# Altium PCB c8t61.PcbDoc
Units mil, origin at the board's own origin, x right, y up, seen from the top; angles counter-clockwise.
Board outline 3290 x 3191.61 mil, 2 copper layers (Top Layer, Bottom Layer); 81 components, 47 nets, 395 pads, 83 vias.
Unrouted connection lines stored in the file: 7.
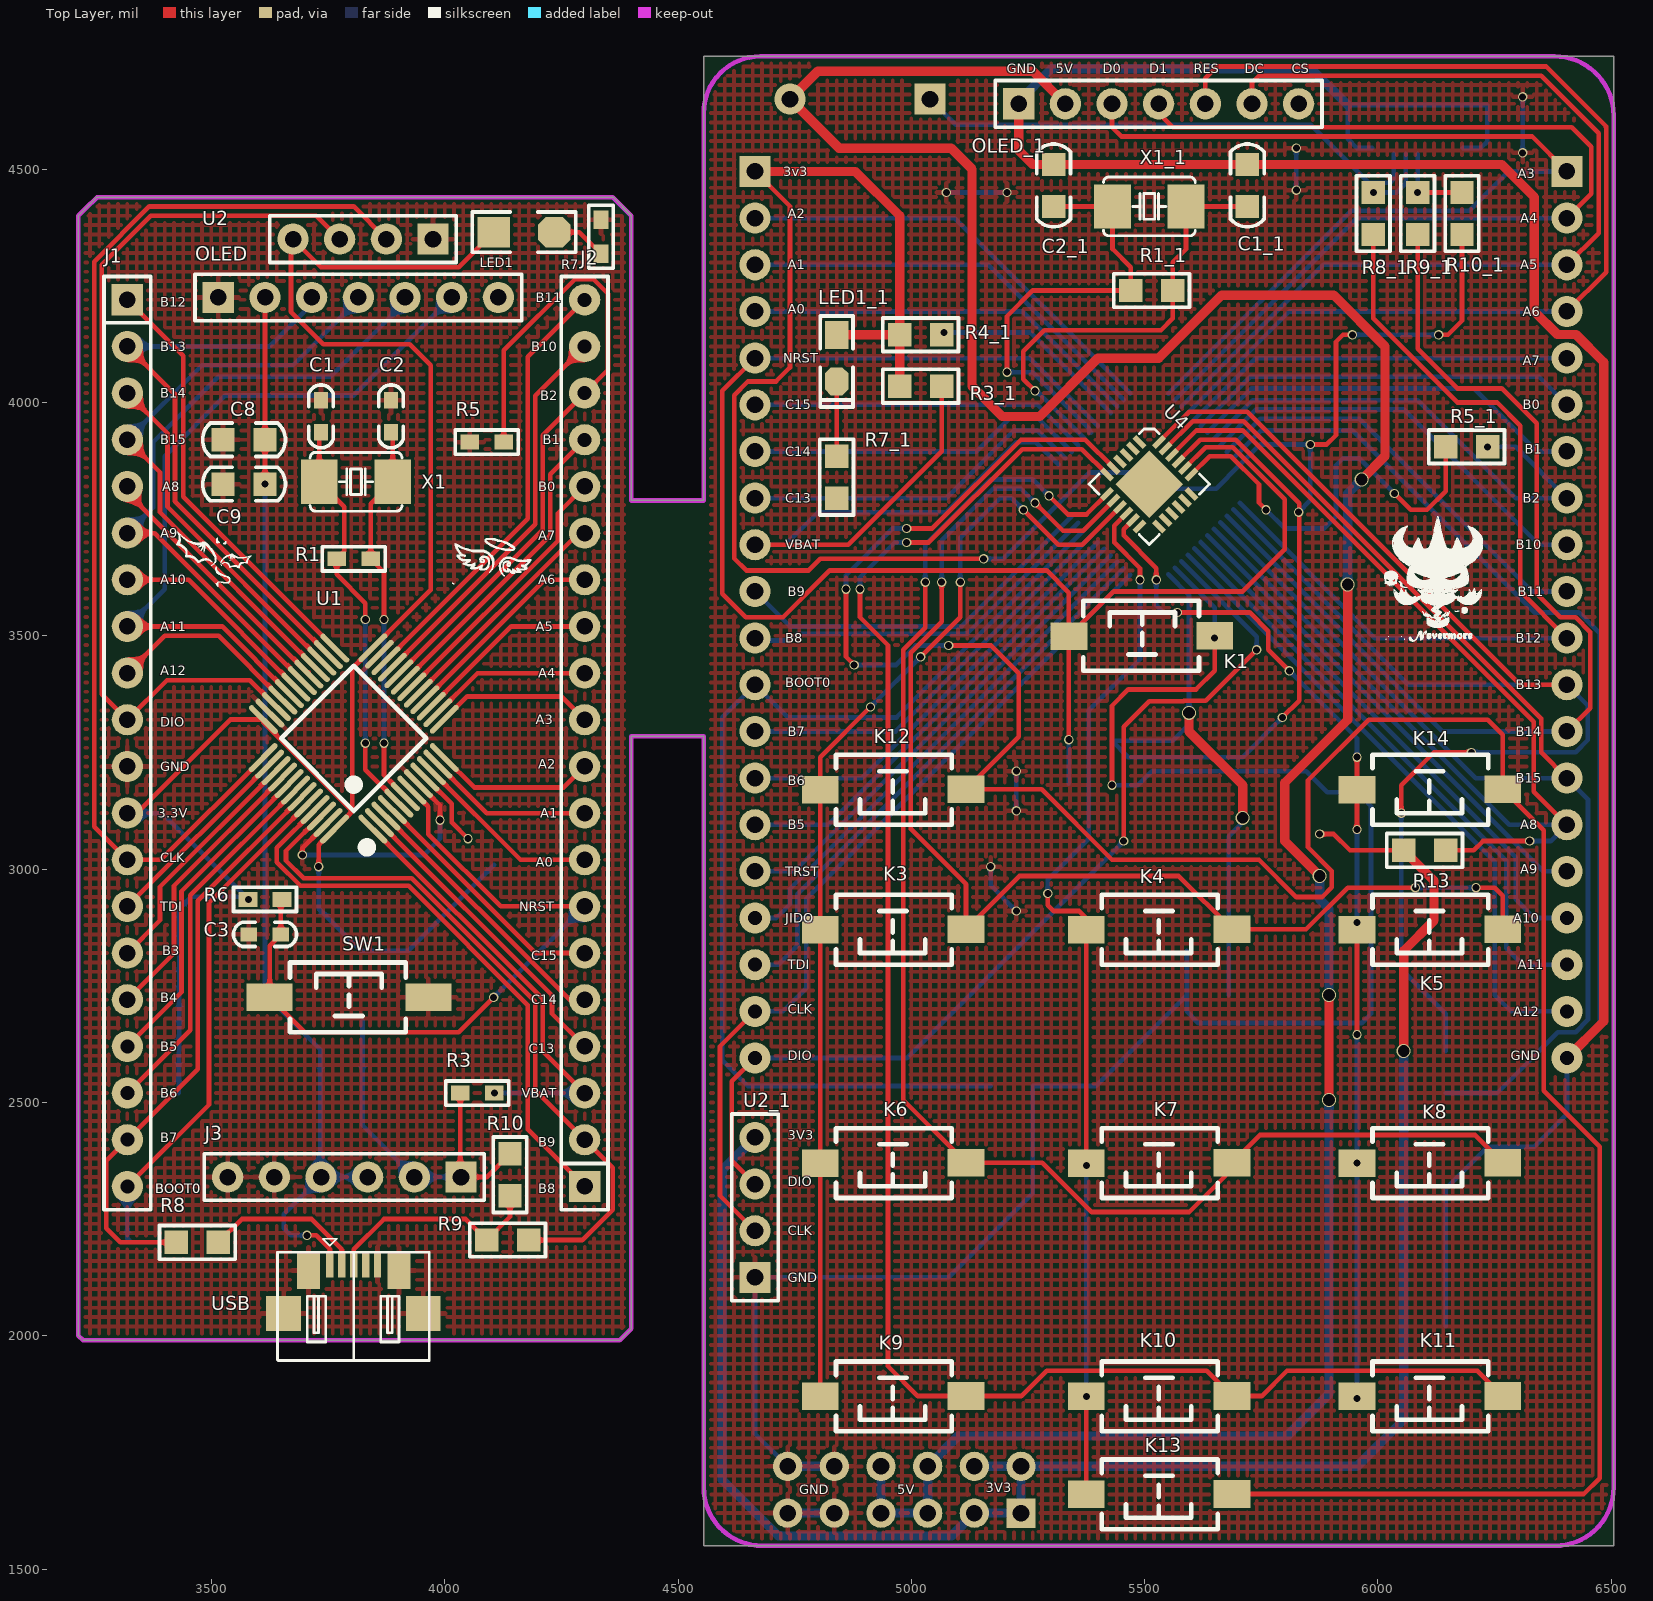
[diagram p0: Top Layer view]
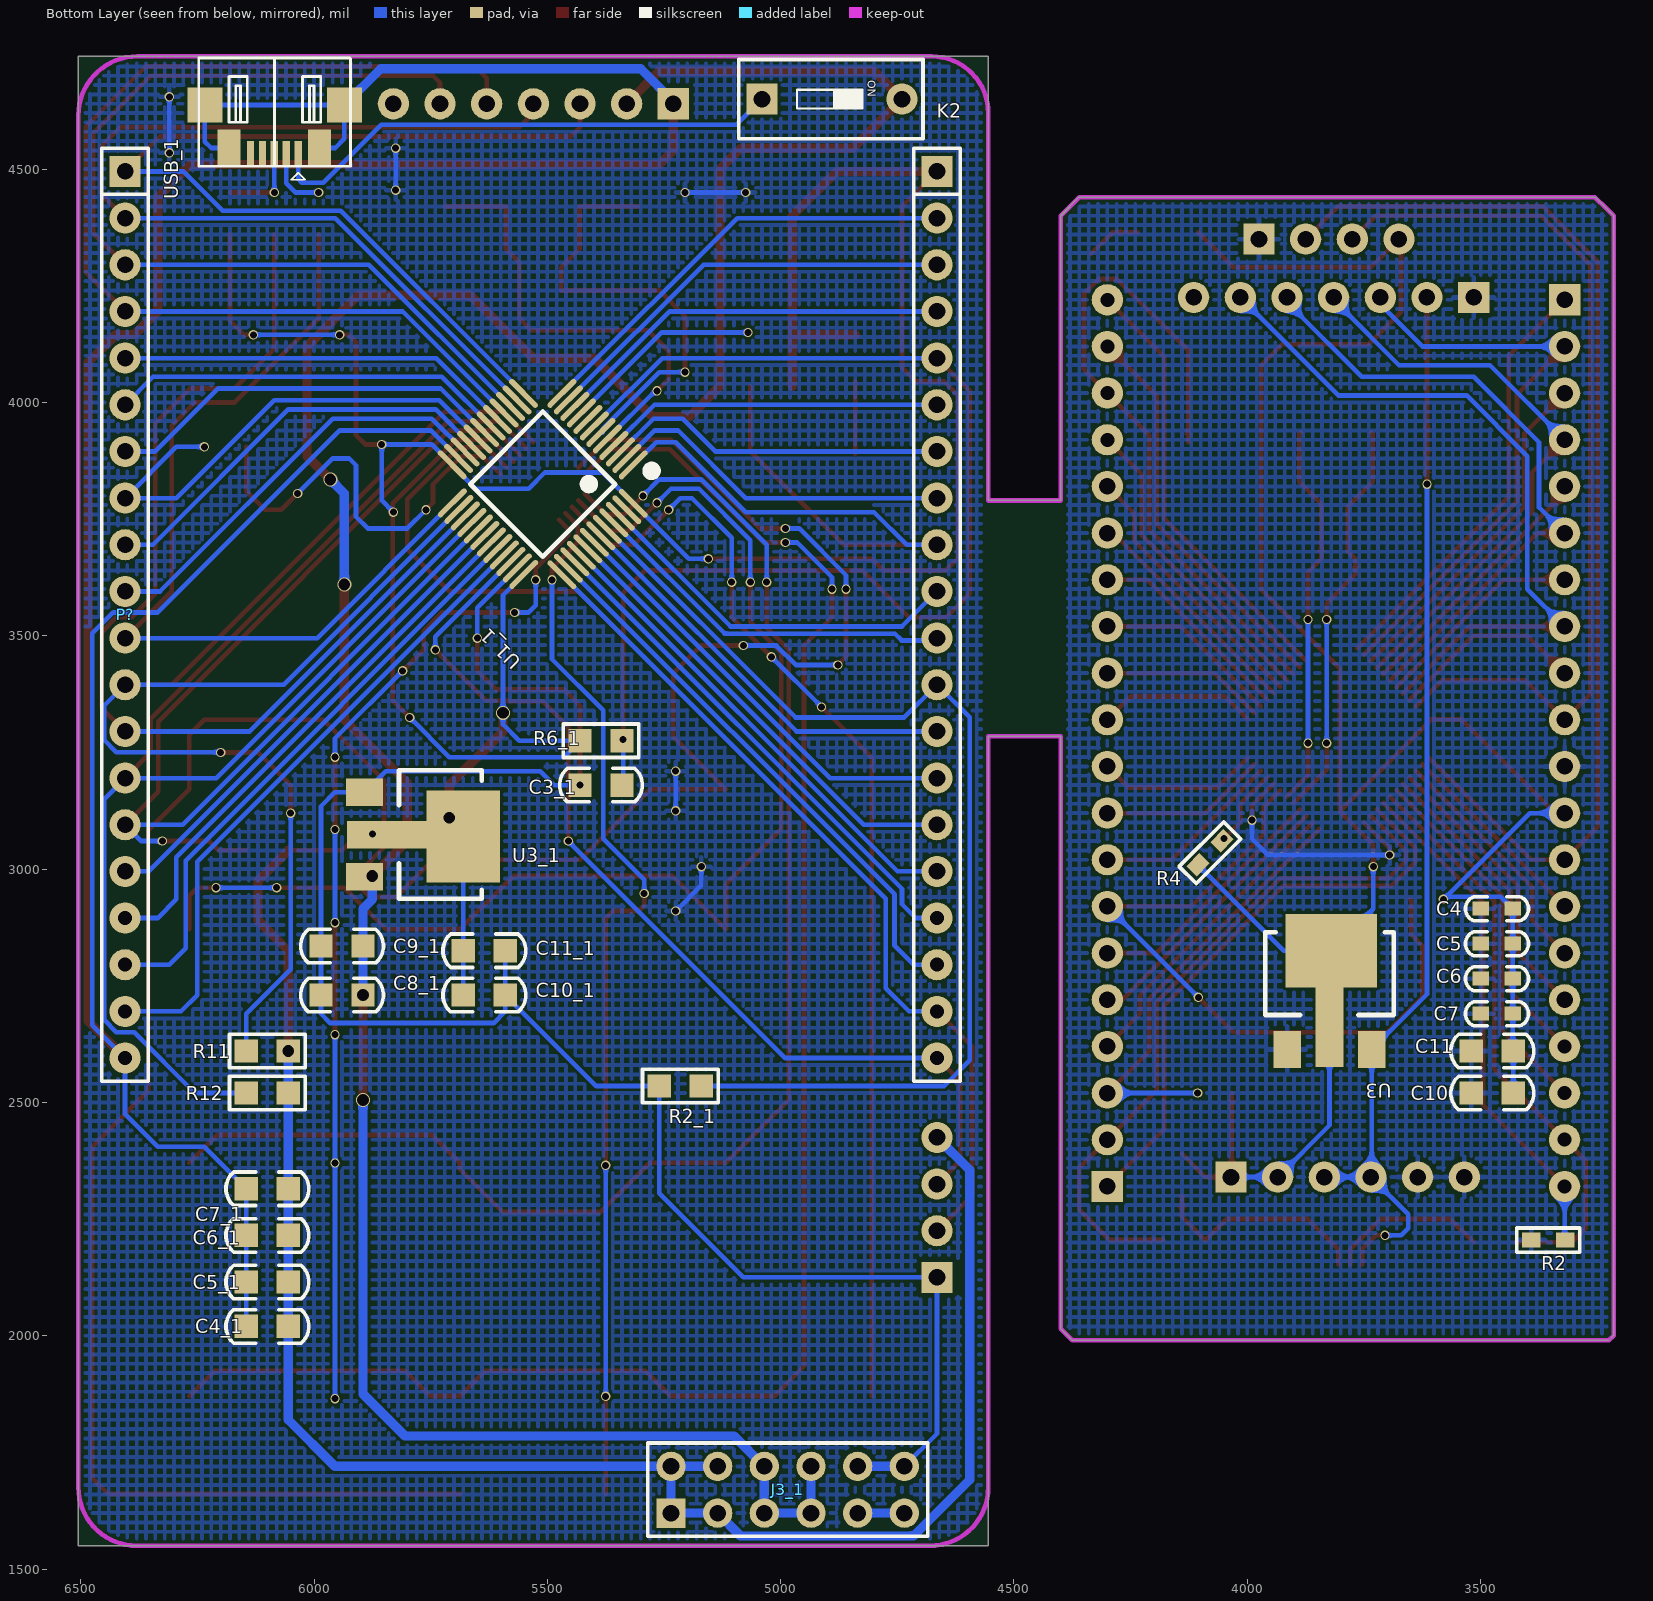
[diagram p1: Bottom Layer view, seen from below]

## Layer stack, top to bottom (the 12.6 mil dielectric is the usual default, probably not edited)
Top Solder: solder mask 0.4, Solder Resist, Dk 3.5
Top Layer: signal copper 1.4
Dielectric 1: dielectric 12.6, FR-4, Dk 4.8
Bottom Layer: signal copper 1.4
Bottom Solder: solder mask 0.4, Solder Resist, Dk 3.5

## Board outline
3215,2000 3225,1990 4375,1990 4400,2015 4400,3285 4555,3285 4555,1550 6505,1550 6505,4741.61 4555,4741.61 4555,3790 4400,3790 4400,4400 4360,4440 3255,4440 3230,4415 3215,4400

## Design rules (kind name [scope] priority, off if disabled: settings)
Clearance [All] p1: gap=6 ignorepadtopadclearanceinfootprint=FALSE
PolygonConnect [All] p1: connectstyle=Relief reliefconductorwidth=10 reliefentries=4 polygonreliefangle="90 Angle" airgapwidth=10
RoutingVias [All] p1: holewidth=28 width=50 viastyle="Through Hole" minholewidth=28 minwidth=50 maxholewidth=28 maxwidth=50
SolderMaskExpansion [All] p1: expansion=4
Width [All] p1: maxlimit=20 minlimit=1 preferedwidth=10
30 further rules are at their usual default settings.

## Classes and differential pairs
component class c8t61: C1 C2 C3 C4 C5 C6 C7 C8 C9 C10 C11 J1 J2 J3 LED1 OLED R1 R2 R3 R4 R5 R6 R7 R8 R9 R10 SW1 U1 U2 U3 USB X1

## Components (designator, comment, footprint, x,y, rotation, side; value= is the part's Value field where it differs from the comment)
C1 "22pf" "C 0603" 3735,3970 r270 top
C1_1 "22pf" "C 0805" 5720,4465 r270 top (schematic designator C1)
C2 "22pf" "C 0603" 3885,3970 r270 top
C2_1 "22pf" "C 0805" 5305,4465 r270 top (schematic designator C2)
C3 "104" "C 0603" 3615,2860 r0 top
C3_1 "104" "C 0805" 5385,3180 r180 bottom locked (schematic designator C3)
C4 "104" "C 0603" 3465,2915 r180 bottom
C4_1 "104" "C 0805" 6100,2020 r180 bottom (schematic designator C4)
C5 "104" "C 0603" 3465,2840 r180 bottom
C5_1 "104" "C 0805" 6100,2115 r180 bottom (schematic designator C5)
C6 "104" "C 0603" 3465,2765 r180 bottom
C6_1 "104" "C 0805" 6100,2215 r180 bottom (schematic designator C6)
C7 "104" "C 0603" 3465,2690 r180 bottom
C7_1 "104" "C 0805" 6100,2315 r180 bottom (schematic designator C7)
C8 "10uF" "C 0805" 3570,3920 r0 top
C8_1 "10uF" "C 0805" 5940,2730 r180 bottom locked (schematic designator C8)
C9 "104" "C 0805" 3570,3825 r0 top
C9_1 "104" "C 0805" 5940,2835 r180 bottom locked (schematic designator C9)
C10 "104" "C 0805" 3475,2520 r180 bottom
C10_1 "104" "C 0805" 5635,2730 r0 bottom locked (schematic designator C10)
C11 "10uF" "C 0805" 3475,2610 r180 bottom
C11_1 "10uF" "C 0805" 5635,2825 r0 bottom locked (schematic designator C11)
J1 "HDR-1X20" HDR-1X20 3320,4220 r270 top
J1 "Header 2X10" HDR-1X20 4665,4495 r270 bottom locked
J2 "HDR-1X20" HDR-1X20 4300,2320 r90 top
J3 "HDR-1X6" HDR-1X6 4035,2340 r180 top
J3_1 "Header 6X2" HDR-6X2 5235,1620 r180 bottom (schematic designator J3)
K1 "3x6x5" "TSW SMD-3*6*2.5" 5495,3500 r0 top locked
K2 "KEY_M" "CSW DIP-1P_G" 4890,4650 r270 bottom
K3 "3x6x5" "TSW SMD-3*6*2.5" 4960,2870 r180 top locked
K4 "3x6x5" "TSW SMD-3*6*2.5" 5530,2870 r180 top locked
K5 "3x6x5" "TSW SMD-3*6*2.5" 6110,2870 r180 top locked
K6 "3x6x5" "TSW SMD-3*6*2.5" 4960,2370 r180 top locked
K7 "3x6x5" "TSW SMD-3*6*2.5" 5530,2370 r180 top
K8 "3x6x5" "TSW SMD-3*6*2.5" 6110,2370 r180 top
K9 "3x6x5" "TSW SMD-3*6*2.5" 4960,1870 r180 top locked
K10 "3x6x5" "TSW SMD-3*6*2.5" 5530,1870 r180 top
K11 "3x6x5" "TSW SMD-3*6*2.5" 6110,1870 r180 top
K12 "3x6x5" "TSW SMD-3*6*2.5" 4960,3170 r180 top
K13 "3x6x5" "TSW SMD-3*6*2.5" 5530,1660 r180 top
K14 "3x6x5" "TSW SMD-3*6*2.5" 6110,3170 r180 top
LED1 "SS24" "LED 1206G" 4170,4365 r0 top
LED1_1 "红色" "LED 0805G" 4840,4095 r270 top (schematic designator LED1)
OLED "HDR-1X7" HDR-1X7 3515,4225 r0 top
OLED_1 "OLED" HDR-1X7_M 5230,4640 r0 top (schematic designator OLED)
P? "J2" HDR-1X20 6405,4495 r270 bottom locked
R1 "1M" "R 0603" 3805,3665 r180 top
R1_1 "1M" "R 0805" 5515,4240 r0 top (schematic designator R1)
R2 "10K" "R 0603" 3355,2205 r0 bottom
R2_1 "10K" "R 0805" 5215,2535 r180 bottom (schematic designator R2)
R3 "0" "R 0603" 4070,2520 r180 top
R3_1 "0" "R 0805" 5020,4035 r180 top (schematic designator R3)
R4 "0" "R 0603" 4080,3035 r135 bottom
R4_1 "0" "R 0805" 5020,4145 r180 top (schematic designator R4)
R5 "10K" "R 0603" 4090,3915 r0 top
R5_1 "10K" "R 0805" 6190,3905 r180 top (schematic designator R5)
R6 "10K" "R 0603" 3615,2935 r0 top
R6_1 "10K" "R 0805" 5385,3275 r0 bottom locked (schematic designator R6)
R7 "1K" "R 0603" 4335,4355 r90 top
R7_1 "1K" "R 0805" 4840,3840 r90 top (schematic designator R7)
R8 "22" "R 0805" 3470,2200 r180 top
R8_1 "22" "R 0805" 5990,4405 r270 top (schematic designator R8)
R9 "22" "R 0805" 4135,2205 r0 top
R9_1 "22" "R 0805" 6085,4405 r270 top (schematic designator R9)
R10 "1.5K" "R 0805" 4140,2345 r90 top
R10_1 "1.5K" "R 0805" 6180,4405 r270 top (schematic designator R10)
R11 "4.7K" "R 0805" 6100,2610 r0 bottom
R12 "4.7K" "R 0805" 6100,2520 r0 bottom
R13 "4.7K" "R 0805" 6100,3040 r0 top
SW1 "CSW-1P" "TSW SMD-3*6*5" 3795,2725 r0 top
U1 "STM32F103C8T6" "LQFP48 7X7_M" 3805,3280 r45 top
U1_1 "STM32F103C8T6" "LQFP48 7X7_M" 5510,3825 r45 bottom locked (schematic designator U1)
U2 "HDR-1X4" HDR-1X4 3975,4350 r180 top
U2_1 "HDR-1X4" HDR-1X4 4665,2125 r90 top (schematic designator U2)
U3 "LM1117MPX" SOT-223-4 3823.94,2719.19 r270 bottom
U3_1 "LM1117MPX" SOT-223-4 5785.81,3073.94 r0 bottom locked (schematic designator U3)
U4 "TCA8418" QFN24 5509.87,3824.88 r315 top
USB "USB-5P" USB-MICRO_A 3805,2060 r0 top
USB_1 "USB-5P" USB-MICRO_A 6085,4625 r0 bottom (schematic designator USB)
X1 "8MHz" SMD5032-2 3810,3830 r180 top
X1_1 "8MHz" SMD5032-2 5510,4420 r0 top (schematic designator X1)

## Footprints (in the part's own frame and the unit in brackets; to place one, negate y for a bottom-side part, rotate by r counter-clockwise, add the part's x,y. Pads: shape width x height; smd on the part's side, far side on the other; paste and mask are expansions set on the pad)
"C 0603" [mil] "无极性贴片电容"
  rect 35x30 smd: 1(-35,0) 2(34,0)
  silkscreen extent -67,-26 67,26, body extent -31,-16 31,16, height 32
"C 0805" [mil] "无极性贴片电容"
  rect 50x50 smd: 1(-45,0) 2(45,0)
  silkscreen extent -89,-36 89,36, body extent -39,-24 39,24, height 20
"CSW DIP-1P_G" [mm] "4.1*9.9*7mm"
  rect 1.7x1.7 hole 0.9: 1(0,-3.81)
  round 1.7 hole 0.9: 2(0,3.81)
  silkscreen extent -2.16,-5.08 2.16,4.95, body extent -2.05,-4.95 2.05,4.95, height 6.65
HDR-1X4 [mm] "排针，4脚"
  rect 1.7x1.7 hole 0.9: 1(0,0)
  round 1.7 hole 0.9: 2(2.54,0) 3(5.08,0) 4(7.62,0)
  silkscreen extent -1.27,-1.27 8.89,1.27, body extent -1.27,-1.27 8.89,1.27, height 8.5
HDR-1X6 [mm] "排针，6脚"
  rect 1.7x1.7 hole 0.9: 1(0,0)
  round 1.7 hole 0.9: 2(2.54,0) 3(5.08,0) 4(7.62,0) 5(10.16,0) 6(12.7,0)
  silkscreen extent -1.27,-1.27 13.97,1.27, body extent -1.27,-1.27 13.97,1.27, height 8.5
HDR-1X7 [mm] "排针，8脚"
  rect 1.7x1.7 hole 0.9: 1(0,0)
  round 1.7 hole 0.9: 2(2.54,0) 3(5.08,0) 4(7.62,0) 5(10.16,0) 6(12.7,0) 7(15.24,0)
  silkscreen extent -1.27,-1.27 16.51,1.27, body extent -1.27,-1.27 16.51,1.27, height 8.5
HDR-1X7_M [mm] "排母，7脚"
  rect 1.7x1.7 hole 0.9: 1(0,0)
  round 1.7 hole 0.9: 2(2.54,0) 3(5.08,0) 4(7.62,0) 5(10.16,0) 6(12.7,0) 7(15.24,0)
  silkscreen extent -1.27,-1.27 16.51,1.27, body extent -1.27,-1.27 16.51,1.27, height 8.5
HDR-1X20 [mm] "排针，20脚"
  rect 1.7x1.7 hole 0.9: 1(0,0)
  round 1.7 hole 0.9: 2(2.54,0) 3(5.08,0) 4(7.62,0) 5(10.16,0) 6(12.7,0) 7(15.24,0) 8(17.78,0) 9(20.32,0) 10(22.86,0) 11(25.4,0) 12(27.94,0) 13(30.48,0) 14(33.02,0) 15(35.56,0) 16(38.1,0)
  round 1.7 hole 0.762: 17(40.64,0) 18(43.18,0) 19(45.72,0) 20(48.26,0)
  silkscreen extent -1.27,-1.27 49.53,1.27, body extent -1.27,-1.27 49.53,1.27, height 8.5
HDR-6X2 [mm] "双排排针，6x2脚"
  rect 1.6x1.6 hole 0.9: 1(0,0)
  round 1.6 hole 0.9: 2(0,2.54) 3(2.54,0) 4(2.54,2.54) 5(5.08,0) 6(5.08,2.54) 7(7.62,0) 8(7.62,2.54) 9(10.16,0) 10(10.16,2.54) 11(12.7,0) 12(12.7,2.54)
  silkscreen extent -1.27,-1.27 13.97,3.81, body extent -1.27,-1.27 13.97,3.81, height 8.5
"LED 0805G" [mil] "绿色0805LED"
  rect 60x50 smd: 1(-50,0)
  oct 60x50 smd: 2(50,0)
  silkscreen extent -90,-35 105,35, body extent -39,-25 39,25, height 32
"LED 1206G" [mil] "绿色1206LED"
  rect 70x65 smd: 1(-65,0)
  oct 70x65 smd: 2(65,0)
  silkscreen extent -111,-43 111,43, body extent -63,-32 63,32, height 40
"LQFP48 7X7_M" [mm] "48脚，体宽7x7mm，脚距0.5mm"
  oval 0.3x2.1 smd: 1(-2.75,-4.227) 2(-2.25,-4.227) 3(-1.75,-4.227) 4(-1.25,-4.227) 5(-0.75,-4.227) 6(-0.25,-4.227) 7(0.25,-4.227) 8(0.75,-4.227) 9(1.25,-4.227) 10(1.75,-4.227) 11(2.25,-4.227) 12(2.75,-4.227) 25(2.75,4.202) 26(2.25,4.202) 27(1.75,4.202) 28(1.25,4.202) 29(0.75,4.202) 30(0.25,4.202) 31(-0.25,4.202) 32(-0.75,4.202) 33(-1.25,4.202) 34(-1.75,4.202) 35(-2.25,4.202) 36(-2.75,4.202)
  oval 2.1x0.3 smd: 13(4.227,-2.75) 14(4.227,-2.25) 15(4.227,-1.75) 16(4.227,-1.25) 17(4.227,-0.75) 18(4.227,-0.25) 19(4.227,0.25) 20(4.227,0.75) 21(4.227,1.25) 22(4.227,1.75) 23(4.227,2.25) 24(4.227,2.75) 37(-4.227,2.75) 38(-4.227,2.25) 39(-4.227,1.75) 40(-4.227,1.25) 41(-4.227,0.75) 42(-4.227,0.25) 43(-4.227,-0.25) 44(-4.227,-0.75) 45(-4.227,-1.25) 46(-4.227,-1.75) 47(-4.227,-2.25) 48(-4.227,-2.75)
  silkscreen extent -3.93,-4.95 2.79,2.79, body extent -4.5,-4.5 4.5,4.5, height 1.45
QFN24 [mm]
  rect 0.8x0.3 smd: 1(-2,1.25) 2(-2,0.75) 3(-2,0.25) 4(-2,-0.25) 5(-2,-0.75) 6(-2,-1.25) 13(2,-1.25) 14(2,-0.75) 15(2,-0.25) 16(2,0.25) 17(2,0.75) 18(2,1.25)
  rect 0.3x0.8 smd: 7(-1.25,-2) 8(-0.75,-2) 9(-0.25,-2) 10(0.25,-2) 11(0.75,-2) 12(1.25,-2) 19(1.25,2) 20(0.75,2) 21(0.25,2) 22(-0.25,2) 23(-0.75,2) 24(-1.25,2)
  rect 2.6x2.6 smd: 25(0.005,0)
  silkscreen extent -2.32,-2.32 2.32,2.32, body extent -2,-2 2.01,2, height 0.9
"R 0603" [mil] "1/10W贴片电阻"
  rect 40x31.5 smd: 1(-36.5,0) 2(36.5,0)
  silkscreen extent -68,-26 68,26, body extent -31,-16 32,16, height 16
"R 0805" [mil] "1/8W贴片电阻"
  rect 50x50 smd: 1(-45,0) 2(45,0)
  silkscreen extent -81,-36 81,36, body extent -39,-25 39,25, height 20
SMD5032-2 [mm]
  rect 2x2.4 smd: 1(-2,0) 2(2,0)
  silkscreen extent -2.5,-1.6 2.5,1.6
SOT-223-4 [mm]
  rect 2x1.5 smd: 1(2.687,-2.3) 3(2.687,2.3)
  rect 4x5 smd: 2(-2.687,0.1)
  rect 5x1.5 smd: 2(1.137,0)
  silkscreen extent -3.69,-3.5 0.81,3.5
"TSW SMD-3*6*2.5" [mm] "3*6*2.5mm"
  rect 2x1.5 smd: 1(-3.996,-0.02) 2(3.937,0)
  silkscreen extent -3.21,-1.9 3.09,1.9, body extent -4,-1.88 4,1.62, height 2.59
"TSW SMD-3*6*5" [mm] "3*6*5mm"
  rect 2.5x1.5 smd: 1(-4.318,0) 2(4.318,0)
  silkscreen extent -3.21,-1.9 3.09,1.9, body extent -4.6,-1.75 4.6,1.75, height 5.1
USB-MICRO_A [mm] "micro型USB ，5.9*8.2*2.5mm"
  rect 0.4x1.4 smd: 1(-1.296,2.355) 2(-0.648,2.355) 3(0,2.355) 4(0.648,2.355) 5(1.295,2.355)
  rect 1.9x1.9 smd: 5(-3.81,-0.312) 5(3.784,-0.312)
  rect 1.25x2 smd: 5(-2.464,2.025) 5(2.464,2.025)
  silkscreen extent -4.14,-2.89 4.11,3.75, body extent -3.98,-2.77 3.98,2.65, height 2.69

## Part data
C1 C1_1 C2 C2_1 C3 C3_1 C4 C4_1 C5 C5_1 C6 C6_1 C7 C7_1: library part C, "无极性贴片电容"
C8 C8_1 C9 C9_1 C10 C10_1 C11 C11_1: library part C
J1 J2: library part "Header 20", "20P接插件"
J1: library part "Header 10X2", "10*2P接插件"
J3: library part "Header 6", "6P接插件"
J3_1: library part "Header  6X2", "6*2P接插件"
K1 K3 K4 K5 K6 K7 K8 K9 K10 K11 K12 K13 K14: library part "TSW 3x6", "3x6轻触开关"
LED1: "肖特基二极管"
LED1_1: library part LED-SMD, "贴片LED"
OLED: library part "Header 7", "7P接插件"
P?: library part "Header 10X2", "Header, 10-Pin, Dual row"
R1 R2 R2_1 R3 R3_1 R4 R4_1 R5 R5_1 R6 R6_1 R7 R7_1 R11 R12 R13: library part R, "贴片电阻"
R1_1: library part R-CRR, "直插色环电阻"
R8 R8_1 R9 R9_1 R10 R10_1: library part R
SW1: "2路编码开关"
U1 U1_1: "Flaah:64/RAM:20/IO:36"
U2 U2_1: library part "Header 4", "4P接插件"
U3 U3_1: "NS 800mA Low-Dropout Linear Regulator"
U4: library part Component_1
USB USB_1: "微型USB母座"
X1 X1_1: library part XTAL-2, "2脚晶振"

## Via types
v1: diameter 20, hole 15, Top Layer to Bottom Layer, 75 vias
v2: diameter 30, hole 25, Top Layer to Bottom Layer, 8 vias

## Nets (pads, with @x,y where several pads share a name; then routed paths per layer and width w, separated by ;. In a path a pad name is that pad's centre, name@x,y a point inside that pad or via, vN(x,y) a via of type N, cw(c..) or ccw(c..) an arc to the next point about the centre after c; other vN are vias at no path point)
3.3v: C4.2 C5.2 C6.2 C7.2 C10.2 C11.2 J1.12@3320,3120 J3.1 J3.2 LED1.1 R3.2 R4.1 R6.1 R10.2 U1.24 U1.36 U1.48 U2.4 U3.2 | length 5060.3
  Top Layer w10: J1.12@3320,3120 3340,3120 3540.41,3320.41 U1.36 3611.48,3314.18 3801.89,3123.77 U1.48 3730,3051.89 v1(3730,3005) ; 3801.89,3130 3801.89,3430 U1.24 3970,3598.11 3970,4080 3925,4125 3740,4125 3670.54,4194.46 3670.54,4345.54 U2.4 3735,4290 4030,4290 LED1.1 ; R3.2 4033.5,2341.5 J3.1 4090,2340 R10.2
  Bottom Layer w10: J1.12@3320,3120 3395,3120 v1@3574,2941 ; C10.2 C11.2 3431,2611 C7.2 C6.2 C5.2 C4.2 3457,2941 v1@3574,2941 ; v1(3580,2935) v1@3574,2941 ; v1(3730,3005) 3730,2915 3820,2825 3921.62,2825 R4.1 ; U3.2@3823.94,2674.41 3823.94,2451.06 J3.2 J3.1
5v: C8.2 C9.2 J3.3 J3.4 OLED.2 U3.3 USB.1 | length 2328.3
  Top Layer w10: v1(3615,3825) C8.2 OLED.2 ; v1(3705,2215) 3725,2215 3753.99,2186.01 USB.1
  Bottom Layer w10: v1(3615,3825) 3615,2731.77 U3.3 3733.39,2341.61 J3.4 ; v1(3705,2215) 3670,2215 3655,2230 3655,2260 J3.4 ; J3.3 J3.4
BOOT0: J1.20@3320,2320 R2.1 U1.44 | length 1098.7
  Top Layer w10: J1.20@3320,2320 3495,2495 3495,2928.24 U1.44
  Bottom Layer w10: J1.20@3320,2320 3320,2208.5 R2.1@3323.5,2205
CLK: J1.13@3320,3020 U1.37 U2.2 | length 2396.5
  Top Layer w10: U1.37 3391.89,3020 3320,3020 3249,3091 3249,4301.63 3367.37,4420 3805,4420 U2.2
DIO: J1.10@3320,3320 U1.34 U2.3 | length 1950
  Top Layer w10: U1.34 3582.56,3405 3405,3405 3320,3320 3265,3375 3265,4295 3370,4400 3725,4400 U2.3
GND: C1.1 C2.1 C3.1 C4.1 C5.1 C6.1 C7.1 C8.1 C9.1 C10.1 C11.1 J1.11@3320,3220 J3.5 J3.6 J3_1.9 J3_1.10 J3_1.11 J3_1.12 OLED.1 OLED_1.1 P?.20 R2.2 R5.1 R7.2 SW1.2 U1.8 U1.23 U1.35 U1.47 U2.1 U2_1.1 U3.1 USB.5 | length 1082.2
  Top Layer w10: v1(3695,3030) 3695,3044.73 U1.47 ; U1.8 3990,3136.76 v1(3990,3105)
  Bottom Layer w10: v1(3695,3030) 3955,3030 3990,3065 v1(3990,3105) ; v1(5075,4450) v1(5205,4450) ; v1(5170,3005) 5170,2965 v1(5225,2910) ; v1(5225,3125) v1(5225,3210) ; v1(5825,4455) v1(5825,4545) ; v1(6310,4535) v1(6310,4655)
  other v1: 5430,3180 5650,3495 5760,3770 6035,3805
JTDO/PB3: J1.15@3320,2820 U1.39 | length 523
  Top Layer w10: J1.15@3320,2820 3390,2890 3390,2962.44 U1.39
NetLED1_2: LED1.2 R7.1 | length 119.3
  Top Layer w10: LED1.2 4288.5,4365 R7.1
NetR8_1: R8.1 USB.2 | length 344.7
  Top Layer w10: R8.1 3565,2250 3715,2250 3779.49,2185.51 USB.2
NetR9_1: R9.1 R10.1 USB.3 | length 478.6
  Top Layer w10: USB.3 3804.99,2184.99 3870,2250 4045,2250 R9.1 4140,2255 R10.1
NRST: C3.2 J2.7 R6.2 SW1.1 U1.7 | length 1547
  Top Layer w10: R6.2 3649,2932.5 C3.2 3625,2836 SW1.1 3700,2650 4030,2650 v1(4105,2725) ; U1.7 3965,3133.92 3965,3075 4120,2920 J2.7
  Bottom Layer w10: v1(4105,2725) J2.7
"OSC IN": C1.2 R1.2 U1.5 X1.2 | length 880.4
  Top Layer w10: C1.2 3731.26,3932.26 X1.2 3785,3776.26 3785,3681.5 R1.2 3768.5,3631.5 3830,3570 v1(3830,3535) ; v1(3830,3270) 3830,3213.24 U1.5
  Bottom Layer w10: v1(3830,3270) v1(3830,3535)
"OSC OUT": C2.2 R1.1 U1.6 X1.1 | length 832.5
  Top Layer w10: v1(3870,3270) 3870,3201.08 U1.6 ; v1(3870,3535) 3870,3636.5 R1.1 3841.5,3782.76 X1.1 3888.74,3932.26 C2.2
  Bottom Layer w10: v1(3870,3270) v1(3870,3535)
PA0: J2.8 U1.10 | length 407.7
  Top Layer w10: U1.10 4162.44,3020 J2.8
PA1: J2.9 U1.11 | length 358.2
  Top Layer w10: U1.11 4090.27,3120 J2.9
PA2: J2.10 U1.12 | length 372.6
  Top Layer w10: U1.12 4063.11,3175 4255,3175 J2.10 J2.10@4281.12,3238.88
PA3: J2.11 U1.13 | length 341.7
  Top Layer w10: U1.13 4048.11,3370 4250,3370 J2.11
PA4: J2.12 U1.14 | length 349.9
  Top Layer w10: U1.14 4070.27,3420 J2.12
PA5: J2.13 U1.15 | length 399.5
  Top Layer w10: U1.15 4142.44,3520 J2.13
PA6: J2.14 U1.16 | length 449
  Top Layer w10: U1.16 4214.6,3620 J2.14
PA7: J2.15 U1.17 | length 498.6
  Top Layer w10: U1.17 4286.76,3720 J2.15
PA8: J1.5@3320,3820 U1.29 | length 567.2
  Top Layer w10: J1.5@3320,3820 3320,3806.76 U1.29 U1.29@3708.91,3421.78
PA9: J1.6@3320,3720 OLED.5 U1.30 | length 1396.7
  Top Layer w10: J1.6@3320,3720 3378.92,3720 U1.30
  Bottom Layer w10: J1.6@3320,3720 3375,3775 3375,3915 3515,4055 3755,4055 3900,4200 OLED.5@3900,4230
PA10: J1.7@3320,3620 U1.31 | length 456.3
  Top Layer w10: J1.7@3320,3620 3451.08,3620 U1.31
PA11: J1.8@3320,3520 OLED.6 U1.32 | length 1570.7
  Top Layer w10: J1.8@3320,3520 3523.24,3520 U1.32
  Bottom Layer w10: J1.8@3320,3520 3400,3600 3400,3885 3530,4015 3805,4015 OLED.6 ; OLED.6@3990,4225 OLED.6@4000,4225
PA12: J1.9@3320,3420 U1.33 | length 423.5
  Top Layer w10: J1.9@3320,3420 3400,3500 3515.4,3500 U1.33
PB0: J2.16 U1.18 | length 582.7
  Top Layer w10: U1.18 4242,3703.08 4242,3762 J2.16
PB1: J2.17 U1.19 | length 674.5
  Top Layer w10: U1.19 4226,3714.92 4226,3846 J2.17
PB2: J2.18 R5.2 U1.20 | length 1496.4
  Top Layer w10: U1.20 4210,3726.76 4210,3930 J2.18 4350,4070 4350,4232.88 4318.42,4264.46 4279.46,4264.46 4126.5,4111.5 R5.2
PB4: J1.16@3320,2720 U1.40 | length 614.9
  Top Layer w10: J1.16@3320,2720 3420,2820 3420,2964.6 U1.40
PB5: J1.17@3320,2620 U1.41 | length 706.7
  Top Layer w10: J1.17@3320,2620 3436,2736 3436,2952.76 U1.41
PB6: J1.18@3320,2520 U1.42 | length 798.6
  Top Layer w10: J1.18@3320,2520 3455,2655 3455,2943.92 U1.42
PB7: J1.19@3320,2420 R8.2 U1.43 | length 1261.5
  Top Layer w10: R8.2 3305,2200 3275,2230 3275,2375 3320,2420 3471,2571 3471,2932.08 U1.43
PB8: J2.1 U1.45 | length 1270.6
  Top Layer w10: U1.45 3640,3045.4 3640,3015 3691,2964 3922.63,2964 4178,2708.63 4178,2442 J2.1 J2.1@4280,2320
PB9: J2.2 R9.2 U1.46 | length 1508.8
  Top Layer w10: U1.46 3734.18,3113.61 3660,3039.42 3660,3017.63 3697.63,2980 3929.26,2980 4194,2715.26 4194,2526 J2.2 4360,2360 4360,2270 4295,2205 R9.2
PB10: J2.19 U1.21 | length 858.2
  Top Layer w10: U1.21 4194,3738.6 4194,4014 J2.19
PB11: J2.20 U1.22 | length 950.1
  Top Layer w10: U1.22 4178,3750.44 4178,4098 J2.20
PB12: J1.1@3320,4220 U1.25 | length 930.6
  Top Layer w10: J1.1@3320,4220 3440,4100 3440,3798.11 U1.25
PB13: J1.2@3320,4120 OLED.3 U1.26 | length 1279.9
  Top Layer w10: J1.2@3320,4120 3422,4018 3422,3788.27 U1.26
  Bottom Layer w10: J1.2@3320,4120 3625,4120 3700,4195 OLED.3@3700,4225
PB14: J1.3@3320,4020 U1.27 | length 746.9
  Top Layer w10: J1.3@3320,4020 3406,3934 3406,3776.44 U1.27
PB15: J1.4@3320,3920 OLED.4 U1.28 | length 1273.5
  Top Layer w10: J1.4@3320,3920 3390,3850 3390,3764.6 U1.28 U1.28@3722.83,3432.17
  Bottom Layer w10: J1.4@3320,3920 3480,4080 3675,4080 3800,4205 OLED.4@3800,4225
PC13: J2.4 U1.2 | length 661.9
  Top Layer w10: U1.2 4230,2729.73 4230,2690 J2.4
PC14: J2.5 U1.3 | length 589.1
  Top Layer w10: U1.3 4267.56,2720 J2.5
PC15: J2.6 U1.4 | length 539.5
  Top Layer w10: U1.4 4195.4,2820 J2.6
TDI: J1.14@3320,2920 U1.38 | length 431.2
  Top Layer w10: J1.14@3320,2920 3320,2920.27 U1.38
VBAT: J2.3 R3.1 U1.1 | length 947.3
  Top Layer w10: U1.1 4210,2721.89 4210,2610 J2.3
  Bottom Layer w10: v1(4106.5,2520) J2.3
VDDA: R4.2 U1.9 | length 170.4
  Top Layer w10: U1.9 4015,3139.6 4015,3100 v1(4050,3065)
pads on no net: C1_1.1 C1_1.2 C2_1.1 C2_1.2 C3_1.1 C3_1.2 C4_1.1 C4_1.2 C5_1.1 C5_1.2 C6_1.1 C6_1.2 C7_1.1 C7_1.2 C8_1.1 C8_1.2 C9_1.1 C9_1.2 C10_1.1 C10_1.2 C11_1.1 C11_1.2 J1.1@4665,4495 J1.2@4665,4395 J1.3@4665,4295 J1.4@4665,4195 J1.5@4665,4095 J1.6@4665,3995 J1.7@4665,3895 J1.8@4665,3795 J1.9@4665,3695 J1.10@4665,3595 J1.11@4665,3495 J1.12@4665,3395 J1.13@4665,3295 J1.14@4665,3195 J1.15@4665,3095 J1.16@4665,2995 J1.17@4665,2895 J1.18@4665,2795 J1.19@4665,2695 J1.20@4665,2595 J3_1.1 J3_1.2 J3_1.3 J3_1.4 J3_1.5 J3_1.6 J3_1.7 J3_1.8 K1.1 K1.2 K2.1 K2.2 K3.1 K3.2 K4.1 K4.2 K5.1 K5.2 K6.1 K6.2 K7.1 K7.2 K8.1 K8.2 K9.1 K9.2 K10.1 K10.2 K11.1 K11.2 K12.1 K12.2 K13.1 K13.2 K14.1 K14.2 LED1_1.1 LED1_1.2 OLED.7 OLED_1.2 OLED_1.3 OLED_1.4 OLED_1.5 OLED_1.6 OLED_1.7 P?.1 P?.2 P?.3 P?.4 P?.5 P?.6 P?.7 P?.8 P?.9 P?.10 P?.11 P?.12 P?.13 P?.14 P?.15 P?.16 P?.17 P?.18 P?.19 R1_1.1 R1_1.2 R2_1.1 R2_1.2 R3_1.1 R3_1.2 R4_1.1 R4_1.2 R5_1.1 R5_1.2 R6_1.1 R6_1.2 R7_1.1 R7_1.2 R8_1.1 R8_1.2 R9_1.1 R9_1.2 R10_1.1 R10_1.2 R11.1 R11.2 R12.1 R12.2 R13.1 R13.2 U1_1.1 U1_1.2 U1_1.3 U1_1.4 U1_1.5 U1_1.6 U1_1.7 U1_1.8 U1_1.9 U1_1.10 U1_1.11 U1_1.12 U1_1.13 U1_1.14 U1_1.15 U1_1.16 U1_1.17 U1_1.18 U1_1.19 U1_1.20 U1_1.21 U1_1.22 U1_1.23 U1_1.24 U1_1.25 U1_1.26 U1_1.27 U1_1.28 U1_1.29 U1_1.30 U1_1.31 U1_1.32 U1_1.33 U1_1.34 U1_1.35 U1_1.36 U1_1.37 U1_1.38 U1_1.39 U1_1.40 U1_1.41 U1_1.42 U1_1.43 U1_1.44 U1_1.45 U1_1.46 U1_1.47 U1_1.48 U2_1.2 U2_1.3 U2_1.4 U3_1.1 U3_1.2 U3_1.3 U4.1 U4.2 U4.3 U4.4 U4.5 U4.6 U4.7 U4.8 U4.9 U4.10 U4.11 U4.12 U4.13 U4.14 U4.15 U4.16 U4.17 U4.18 U4.19 U4.20 U4.21 U4.22 U4.23 U4.24 U4.25 USB.4 USB_1.1 USB_1.2 USB_1.3 USB_1.4 USB_1.5 X1_1.1 X1_1.2
copper on no net: | length 111496
  Top Layer w10: 4665,2225 4590,2300 4590,2620 4665,2695 ; 4665,2325 4615,2375 4615,2545 4665,2595 ; 4665,3695 4865,3695 5065,3895 5065,4035 ; 4665,4095 4595,4025 4595,3590 4645,3540 4725,3540 4825,3640 5290,3640 5337.69,3592.31 5337.69,3499.21 ; 4665,4495 4740,4420 4740,4075 4710,4045 4650,4045 4620.54,4015.54 4620.54,3665.51 4646.05,3640 4780,3640 4805,3665 v1(5155,3665) ; 4805,1870 4805,2370 4805,2870 4805,3170 4805,3240 v1(4912.5,3347.5) ; 4840,3890 4840,4045 ; v1(4860,3600) 4860,3455 v1(4877.5,3437.5) ; v1(4890,3600) 4890,3540 4950,3480 4950,1935 5014.21,1870.79 5117.31,1870.79 5235.79,1870.79 5290,1925 5633.1,1925 5687.31,1870.79 5750.79,1870.79 5805,1925 6213.1,1925 6267.31,1870.79 ; v1(4990,3700) 5037.63,3700 5237.63,3900 5365.15,3900 5419.39,3845.75 ; v1(4990,3730) 5045,3730 5235,3920 5372.98,3920 5433.31,3859.67 ; v1(5020,3455) 5105,3540 v1(5105,3615) ; v1(5030,3615) 5030,3517.33 4983,3470.33 4983,2505.1 5117.31,2370.79 5280.79,2370.79 5386.57,2265 5595,2265 5687.31,2357.31 5687.31,2370.79 5746.53,2430 6208.1,2430 6267.31,2370.79 ; v1(5065,3615) 5065,3529.7 4999,3463.7 4999,3086 5117.31,2967.69 5117.31,2870.79 5231.53,2985 5573.1,2985 5687.31,2870.79 5845.79,2870.79 5935,2960 v1(6080,2960) ; v1(5080,3479) 5171,3479 5230,3420 5230,3283.47 5117.31,3170.79 5279.21,3170.79 5430,3020 5745,3020 5825,2940 5880,2940 5901,2961 5901,2995.77 5850,3046.77 5850,3190 5980,3320 6235,3320 6267.31,3287.69 6267.31,3170.79 6355,3083.1 6355,2525 6475,2405 6475,1695 6440.79,1660.79 5687.31,1660.79 ; v1(5205,4065) 5205,4185 5260,4240 5470,4240 5470,4290 5431.26,4328.74 5431.26,4420 5305,4420 ; v1(5240,3770) 5315,3695 5366.07,3695 5447.23,3776.16 ; v1(5265,3785) 5325,3725 5368.23,3725 5433.31,3790.08 ; v1(5265,4025) 5240,4050 5240,4110 5285,4155 5535,4155 5560,4180 5560,4240 5560,4300 5588.74,4328.74 5588.74,4420 5720,4420 ; v1(5292.5,2947.5) 5292.5,2922.5 5305,2910 5360,2910 5375,2895 5375,2870 5375,2370 v1(5375,2365) ; v1(5295,3800) 5335,3760 5375.39,3760 5419.39,3804 ; v1(5337.69,3277.31) 5337.69,3499.21 ; 5375,1660 v1(5375,1870) ; 5430,3180 5430,3350 5465,3385 5610,3385 5650,3425 5650,3495 5650,3500 ; 5430,4640 5430,4590 5450,4570 6330,4570 6405,4495 ; v1(5455,3060) 5455,3305 5510,3360 5583.23,3360 5584.23,3361 5631,3361 v1(5740,3470) ; 5461.15,3762.24 5435,3736.09 5435,3700 5490,3645 v1(5490,3620) ; 5475.07,3748.32 5455,3728.25 5455,3715 5525,3645 v1(5525,3620) ; 5530,4640 5530,4620 5560,4590 6415,4590 6457,4548 6457,4447 6405,4395 ; 5530.75,3915.35 5595.39,3980 5720,3980 6305,3395 6405,3395 ; 5544.67,3901.43 5603.23,3960 5712.63,3960 6350,3322.63 6350,3250 6405,3195 ; 5558.58,3887.51 5611.07,3940 5710,3940 6334,3316 6334,3166 6405,3095 ; v1(5570,3550) 5725,3550 5765,3510 5765,3470 v1(5810,3425) ; 5572.5,3873.59 5618.91,3920 5695,3920 5831,3784 5831,3361 v1(5795,3325) ; 5586.42,3859.67 5630.75,3904 5688.37,3904 5800,3792.37 5800,3685 5710,3595 5433.47,3595 5337.69,3499.21 ; 5600.34,3845.75 5639.59,3885 5684.75,3885 5745,3824.75 5745,3785 5760,3770 ; 5630,4640 5630,4695 5655,4720 6360,4720 6488.72,4591.28 6488.72,4589.69 6489,4589.41 6489,4279 6405,4195 ; 5730,4640 5730,4685 5745,4700 6350,4700 6473,4577 6473,4363 6405,4295 6407,4295 ; v1(5855,3910) 5890,3910 5910,3930 5910,4130 5925,4145 v1(5945,4145) ; v1(5875,3075) 5905,3075 5940,3040 6055,3040 ; v1(5955,2645) 5955,2870 v1(5955,2885) ; v1(5955,3085) 5955,3170 v1(5955,3240) ; 5990,4360 5990,4180 6170,4000 6255,4000 6305,3950 6305,3595 6405,3495 ; 6035,3805 6070,3770 6105,3770 6145,3810 6145,3905 ; v1(6050,3120) 6050,3180 6120,3250 v1(6200,3250) ; 6085,4360 6085,4115 6170,4030 6265,4030 6340,3955 6340,3590 6390.54,3539.46 6423.42,3539.46 6455,3507.88 6455,3345 6405,3295 ; v1(6085,4450) 6180,4450 ; v1(6130,4145) 6150,4145 6180,4175 6180,4360 ; 6145,3040 6205,3040 6225,3060 v1(6325,3060) ; v1(6210,2960) 6250,2960 6267.31,2942.69 6267.31,2870.79
  Top Layer w20: 4665,4495 4880,4495 4975,4400 4975,4145 ; 4840,4145 4975,4145 ; 4975,4035 4975,4145 ; 5230,4640 5230,4540 5260,4510 5305,4510 5720,4510 6265,4510 6335,4440 6335,4195.05 6384.51,4145.54 6424.42,4145.54 6484,4085.95 6484,2674 6405,2595 ; 5330,4640 5260,4710 4800,4710 4740,4650 4845,4545 5085,4545 5130,4500 5130,4035 5195,3970 5275,3970 5400,4095 5530,4095 5665,4230 5905,4230 6015,4120 6015,3885 v2(5965,3835) ; v2(5595,3335) 5595,3295 5710,3180 v2(5710,3110) ; v2(5875,2985) 5800,3060 5800,3185 5935,3320 v2(5935,3610) ; v2(5895,2505) v2(5895,2730) ; v2(6055,2610) 6055,2825 6120,2890 6120,2975 6055,3040
  Bottom Layer w10: 4665,2595 4990,2595 v1(5455,3060) ; 4665,2695 4725,2695 4775,2745 4775,2936.89 5468.88,3630.77 ; 4665,2795 4715,2795 4756,2836 4756,2945.73 5454.96,3644.69 ; 4665,2895 4710,2895 4740,2925 4740,2957.56 5441.04,3658.61 ; 4665,2995 4749.6,2995 5427.12,3672.53 ; 4665,3095 4821.76,3095 5413.2,3686.45 ; 4665,3195 4893.92,3195 5399.28,3700.37 ; 4665,3295 4966.08,3295 5385.37,3714.28 ; 4665,3595 4740,3520 5107.56,3520 5343.61,3756.04 ; 4665,3695 4730,3695 4800,3765 5075,3765 5225,3915 5266.89,3915 5315.77,3866.12 ; 4665,3795 5075,3795 5220,3940 5269.73,3940 5329.69,3880.04 ; 4665,3895 5140,3895 5210,3965 5272.56,3965 5343.61,3893.96 ; 4665,3995 5270.4,3995 5357.53,3907.88 ; 4665,4095 5253.92,4095 5399.28,3949.63 ; 4665,4195 5237.44,4195 5441.04,3991.39 ; 4665,4295 5165.27,4295 5454.96,4005.31 ; 4665,4395 5093.11,4395 5468.88,4019.23 ; 4675,3505 4665,3495 4670,3490 4741,3490 4755,3504 5114.19,3504 5115.19,3505 5120.4,3505 5357.53,3742.12 ; 4735,1720 4665,1790 4665,2125 5080,2125 5260,2305 5260,2535 5395,2535 5590,2730 ; v1(4860,3600) 4860,3630 4960,3730 v1(4990,3730) ; v1(4877.5,3437.5) 4967.5,3437.5 5009,3479 v1(5080,3479) ; v1(4890,3600) 4890,3625 4965,3700 v1(4990,3700) ; v1(4912.5,3347.5) v1(5020,3455) ; v1(5030,3615) 5030,3695 5170,3835 5260,3835 v1(5295,3800) ; 5040,4650 5095,4595 5856.26,4595 5980.26,4471 6026,4471 6033.99,4478.99 6033.99,4532.28 ; v1(5065,3615) 5065,3705 5175,3815 5235,3815 v1(5265,3785) ; v1(5070,4150) 5254.6,4150 5427.12,3977.47 ; v1(5105,3615) 5105,3710 5190,3795 5215,3795 v1(5240,3770) ; v1(5155,3665) 5196.89,3665 5315.77,3783.88 5381.89,3850 5505,3850 5540,3815 5653.11,3815 5704.23,3866.12 5748.11,3910 v1(5855,3910) 5855,3790 v1(5830,3765) ; 5170,2535 4650,2535 4595,2590 4595,3325 4665,3395 4735,3325 4968.24,3325 5371.45,3728.2 ; v1(5205,4065) 5260.01,4065 5381.43,3943.58 5381.43,3935.72 5385.37,3935.72 ; v1@5268.24,4025 5371.45,3921.8 ; v1(5292.5,2947.5) 5292.5,2977.5 5380,3065 5380,3340 5490,3450 v1(5490,3620) ; 5337.69,3182.69 v1(5337.69,3277.31) ; v1(5375,1870) v1(5375,2365) ; 5430,3180 5485,3180 5515,3210 5846.1,3210 5891.61,3164.49 5955.51,3164.49 5985,3135 5985,2835 5985,2730 5985,2690 5965,2670 5615,2670 5590,2695 5590,2730 ; v1(5525,3620) 5525,3565 5540,3550 v1(5570,3550) ; 5550.41,3631.48 5595,3586.89 v2(5595,3335) 5595,3310 5560,3275 5430,3275 5465,3240 5710,3240 v1(5795,3325) ; 5551.12,4019.23 5942.89,4411 6196,4411 6280,4495 6405,4495 ; 5564.33,3645.39 5650,3559.73 5650,3495 ; 5565.04,4005.31 5954.73,4395 6405,4395 ; 5578.25,3659.31 5740,3497.56 v1(5740,3470) ; 5578.96,3991.39 5882.56,4295 6405,4295 ; 5590,2825 5590,2730 ; 5592.17,3673.23 6250,3015.4 6250,2730 6285,2695 6405,2695 ; 5592.88,3977.47 5810.4,4195 6405,4195 ; 5606.09,3687.15 6275,3018.24 6275,2830 6310,2795 6405,2795 ; 5606.8,3963.55 5738.24,4095 6405,4095 ; 5620.01,3701.07 5620.01,3699.99 6295,3025 6295,2935 6335,2895 6405,2895 ; 5620.72,3949.63 5726.08,4055 6345,4055 6405,3995 ; 5633.93,3714.99 6353.92,2995 6405,2995 ; 5634.63,3935.72 5728.92,4030 6205,4030 6340,3895 6405,3895 ; 5647.85,3728.91 6281.76,3095 6405,3095 6370,3060 v1(6325,3060) ; 5648.55,3921.8 5731.76,4005 6085,4005 6295,3795 6405,3795 6295,3905 v1(6235,3905) ; 5661.77,3742.83 6209.6,3195 6405,3195 6450,3150 6450,2677.12 6423.42,2650.54 6385.54,2650.54 6255,2520 6145,2520 ; 5662.47,3907.88 5739.6,3985 6055,3985 6345,3695 6405,3695 ; 5675.69,3756.75 6137.44,3295 6405,3295 ; 5676.39,3893.96 5747.44,3965 5960,3965 6330,3595 6405,3595 ; 5680,2730 5680,2825 5680,3070 5710,3100 v2(5710,3110) ; 5689.61,3770.67 6065.27,3395 6405,3395 6449.46,3350.54 6449.46,3276.58 6423.42,3250.54 6200.54,3250.54 v1(6200,3250) ; 5690.31,3880.04 5750.27,3940 5945,3940 6335,3550 6430,3550 6475,3505 6475,2665 6405,2595 6405,2475 6335,2405 6235,2405 6145,2315 6145,2215 6145,2115 6145,2020 ; 5703.52,3784.59 5993.11,3495 6405,3495 ; 5760,3770 5800,3730 5885,3730 5910,3755 5910,3865 5925,3880 5960,3880 6035,3805 ; v1(5810,3425) 5955,3280 v1(5955,3240) ; v1(5945,4145) v1(6130,4145) ; v1(5955,1865) v1(5955,2370) v1(5955,2645) ; v1(5955,2885) v1(5955,3085) ; 5987.99,4545.28 5954.72,4545.28 5934.99,4565.01 5934.99,4637.28 6233.99,4637.28 6233.99,4558.99 6220.28,4545.28 6181.99,4545.28 ; v1(5990,4450) 6040,4450 6059.49,4469.49 6059.49,4532.28 ; v1(6050,3120) 6050,2785 6145,2690 6145,2610 ; v1(6080,2960) v1(6210,2960) ; v1(6085,4450) 6084.99,4532.28
  Bottom Layer w20: 4665,2425 4595,2355 4595,1691.2 4714.78,1571.41 4721.56,1571.41 4721.98,1571 5086,1571 5135,1620 5235,1620 5235,1720 ; 4735,1620 4835,1620 ; 4735,1720 4835,1720 ; 4935,1720 4935,1620 5035,1620 5035,1720 5100,1785 5805,1785 5895,1875 v2(5895,2505) ; 5135,1720 5235,1720 ; 5230,4640 5230,4645 5300,4715 5857.27,4715 5934.99,4637.28 ; v2(5875,2985) 5875,2935 5895,2915 5895,2835 v2(5895,2730) ; v2(5935,3610) 5935,3805 v2(5965,3835) ; v2(6055,2610) 6055,2520 6055,2315 6055,2215 6055,2115 6055,2020 6055,1820 5955,1720 5235,1720

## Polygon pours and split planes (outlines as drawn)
GND on Top Layer "Keep-Out Layer-No Net" (hatched 90Degree grid 20 track 8, remove dead copper, pour order 42): 4520,4870 6855,4870 6880,4845 6740,4705 6740,1315 4510,1315 4470,1355
GND on Top Layer "Keep-Out Layer-No Net" (hatched 90Degree grid 20 track 8, remove dead copper, pour order 28): 3095,4630 3175,4550 4485,4550 4485,1880 4370,1765 4250,1885 2975,1885
GND on Bottom Layer "Keep-Out Layer-No Net" (hatched 90Degree grid 20 track 8, remove dead copper, pour order 44): 2930,4830 2955,4805 6970,4805 6970,1310 6900,1240 6695,1445 2900,1445

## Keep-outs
Keep-Out Layer:
  lines w10: 3215,2000 3215,4350 3215,4400 3230,4415 3255,4440 4360,4440 4400,4400 4400,3790 4555,3790 4555,4620 cw(c4676.61,4620) 4676.61,4741.61 6378.39,4741.61 cw(c6378.39,4615) 6505,4615 6505,1675 cw(c6380,1675) 6380,1550 4680,1550 cw(c4680,1675) 4555,1675 4555,3285 4400,3285 4400,2015 4375,1990 3225,1990 3215,2000

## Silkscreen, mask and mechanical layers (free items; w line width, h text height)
Top Overlay:
  drawing of 2571 lines, arcs and shapes, not listed
  text "GND" at 5205,4705 h20
  text "5V" at 5310,4705 h20
  text "D0" at 5410,4705 h20
  text "D1" at 5510,4705 h20
  text "RES" at 5605,4705 h20
  text "DC" at 5715,4705 h20
  text "CS" at 5815,4705 h20
  text "3v3" at 4725,4485 h20
  text "A3" at 6300,4480 h20
  text "A2" at 4735,4395 h20
  text "A4" at 6305,4385 h20
  text "A1" at 4735,4285 h20
  text "A5" at 6305,4285 h20
  text "B11" at 4195,4215 h20
  text "B12" at 3390,4205 h20
  text "A0" at 4735,4190 h20
  text "A6" at 6310,4185 h20
  text "B13" at 3390,4110 h20
  text "B10" at 4185,4110 h20
  text "NRST" at 4725,4085 h20
  text "A7" at 6310,4080 h20
  text "B14" at 3390,4010 h20
  text "B2" at 4205,4005 h20
  text "C15" at 4730,3985 h20
  text "B0" at 6310,3985 h20
  text "B15" at 3390,3910 h20
  text "B1" at 4210,3910 h20
  text "B1" at 6315,3890 h20
  text "C14" at 4730,3885 h20
  text "A8" at 3395,3810 h20
  text "B0" at 4200,3810 h20
  text "C13" at 4730,3785 h20
  text "B2" at 6310,3785 h20
  text "A9" at 3390,3710 h20
  text "A7" at 4200,3705 h20
  text "VBAT" at 4730,3685 h20
  text "B10" at 6295,3685 h20
  text "A10" at 3390,3610 h20
  text "A6" at 4200,3610 h20
  text "B9" at 4735,3585 h20
  text "B11" at 6300,3585 h20
  text "A11" at 3390,3510 h20
  text "A5" at 4195,3510 h20
  text "B8" at 4730,3485 h20
  text "B12" at 6295,3485 h20
  text "A12" at 3390,3415 h20
  text "A4" at 4200,3410 h20
  text "BOOT0" at 4730,3390 h20
  text "B13" at 6295,3385 h20
  text "A3" at 4195,3310 h20
  text "DIO" at 3390,3305 h20
  text "B7" at 4735,3285 h20
  text "B14" at 6295,3285 h20
  text "A2" at 4200,3215 h20
  text "GND" at 3390,3210 h20
  text "B15" at 6295,3185 h20
  text "B6" at 4735,3180 h20
  text "3.3V" at 3385,3110 h20
  text "A1" at 4205,3110 h20
  text "B5" at 4735,3085 h20
  text "A8" at 6305,3085 h20
  text "CLK" at 3390,3015 h20
  text "A0" at 4195,3005 h20
  text "A9" at 6305,2990 h20
  text "TRST" at 4730,2985 h20
  text "TDI" at 3390,2910 h20
  text "NRST" at 4160,2910 h20
  text "JIDO" at 4730,2885 h20
  text "A10" at 6290,2885 h20
  text "B3" at 3395,2815 h20
  text "C15" at 4185,2805 h20
  text "TDI" at 4735,2785 h20
  text "A11" at 6300,2785 h20
  text "B4" at 3390,2715 h20
  text "C14" at 4185,2710 h20
  text "CLK" at 4735,2690 h20
  text "A12" at 6290,2685 h20
  text "B5" at 3390,2610 h20
  text "C13" at 4180,2605 h20
  text "DIO" at 4735,2590 h20
  text "GND" at 6285,2590 h20
  text "B6" at 3390,2510 h20
  text "VBAT" at 4165,2510 h20
  text "3V3" at 4735,2420 h20
  text "B7" at 3390,2415 h20
  text "B9" at 4200,2405 h20
  text "DIO" at 4735,2320 h20
  text "BOOT0" at 3380,2305 h20
  text "BOOT0" at 3380,2305 h20
  text "B8" at 4200,2305 h20
  text "CLK" at 4735,2215 h20
  text "GND" at 4735,2115 h20
  text "3V3" at 5160,1665 h20
  text "GND" at 4760,1660 h20
  text "5V" at 4970,1660 h20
